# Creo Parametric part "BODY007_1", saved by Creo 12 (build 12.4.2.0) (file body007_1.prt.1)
Units: Custom; MM, KILOGRAM, SECS

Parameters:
  PTC_WM_ITERATION = "0"
  PTC_WM_VERSION = "-.0"
  PTC_WM_LIFECYCLE_STATE = "In Work"
  PTC_WM_LIFECYCLE = "MO_CADDocument"
  PTC_WM_CREATED_BY = "Maximilian Roepper (Z0017RMS: MO)"
  PTC_WM_CREATED_ON = "18-Sep-26 11:36:42 AM"
  PTC_WM_MODIFIED_BY = "Maximilian Roepper (Z0017RMS: MO)"
  PTC_WM_MODIFIED_ON = "18-Sep-26 11:36:46 AM"
  PDMLINKNUMBER = "PDM000071454895"
  PTC_WM_NAME = "body007_1.prt"
  PTC_WM_NUMBER = "PDM000071454895"

Other parameters: WEIGHT, WEIGHT_FACTOR, WEIGHT_ADD, _MASS_TEMP, _DIFF_TEMP, MC_ERRORS, SUPPLIER

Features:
  1. coordinate system
  2. datum plane "PRT_YZ"
  3. datum plane "PRT_XY"
  4. datum plane "PRT_XZ"
  5. coordinate system
  6. datum axis
  7. datum axis
  8. datum axis
  9. coordinate system
  10. imported feature

Other named items: PRT, SIEMENS_MO, DRW_VIEW_ORG, PRT_X, PRT_Y, PRT_Z, CS0, ROUGH_GROB

Layers: 00_STD_CSYS-KSYS, 01_STD_PLANES-EBENEN, 02_STD_AXES-ACHSEN, 03_STD_CSYS-KSYS, 24_IMPORT_FEAT-IMPORT_KE

Surfaces: 6 plane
